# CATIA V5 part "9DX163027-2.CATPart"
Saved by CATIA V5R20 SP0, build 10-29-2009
Part number: 9DX163027-2
Revision: ANY
Definition: UNKNOWN
Nomenclature: 9DX163027-2
Source: Unknown
Bounding box of the stored display mesh (mm): x -16.827 to 16.827, y 0 to 45, z -17 to 17
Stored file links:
  C:\Users\Utente\Desktop\IO LAVORO\3D X SITO CF\CUMSA\3D files DX\DX 163027\9DX163027-2.CATPart
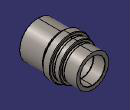
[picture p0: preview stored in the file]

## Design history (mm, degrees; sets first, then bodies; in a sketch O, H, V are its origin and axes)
Body1 "Revolución1" (main body)
  Solid1: solid without history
